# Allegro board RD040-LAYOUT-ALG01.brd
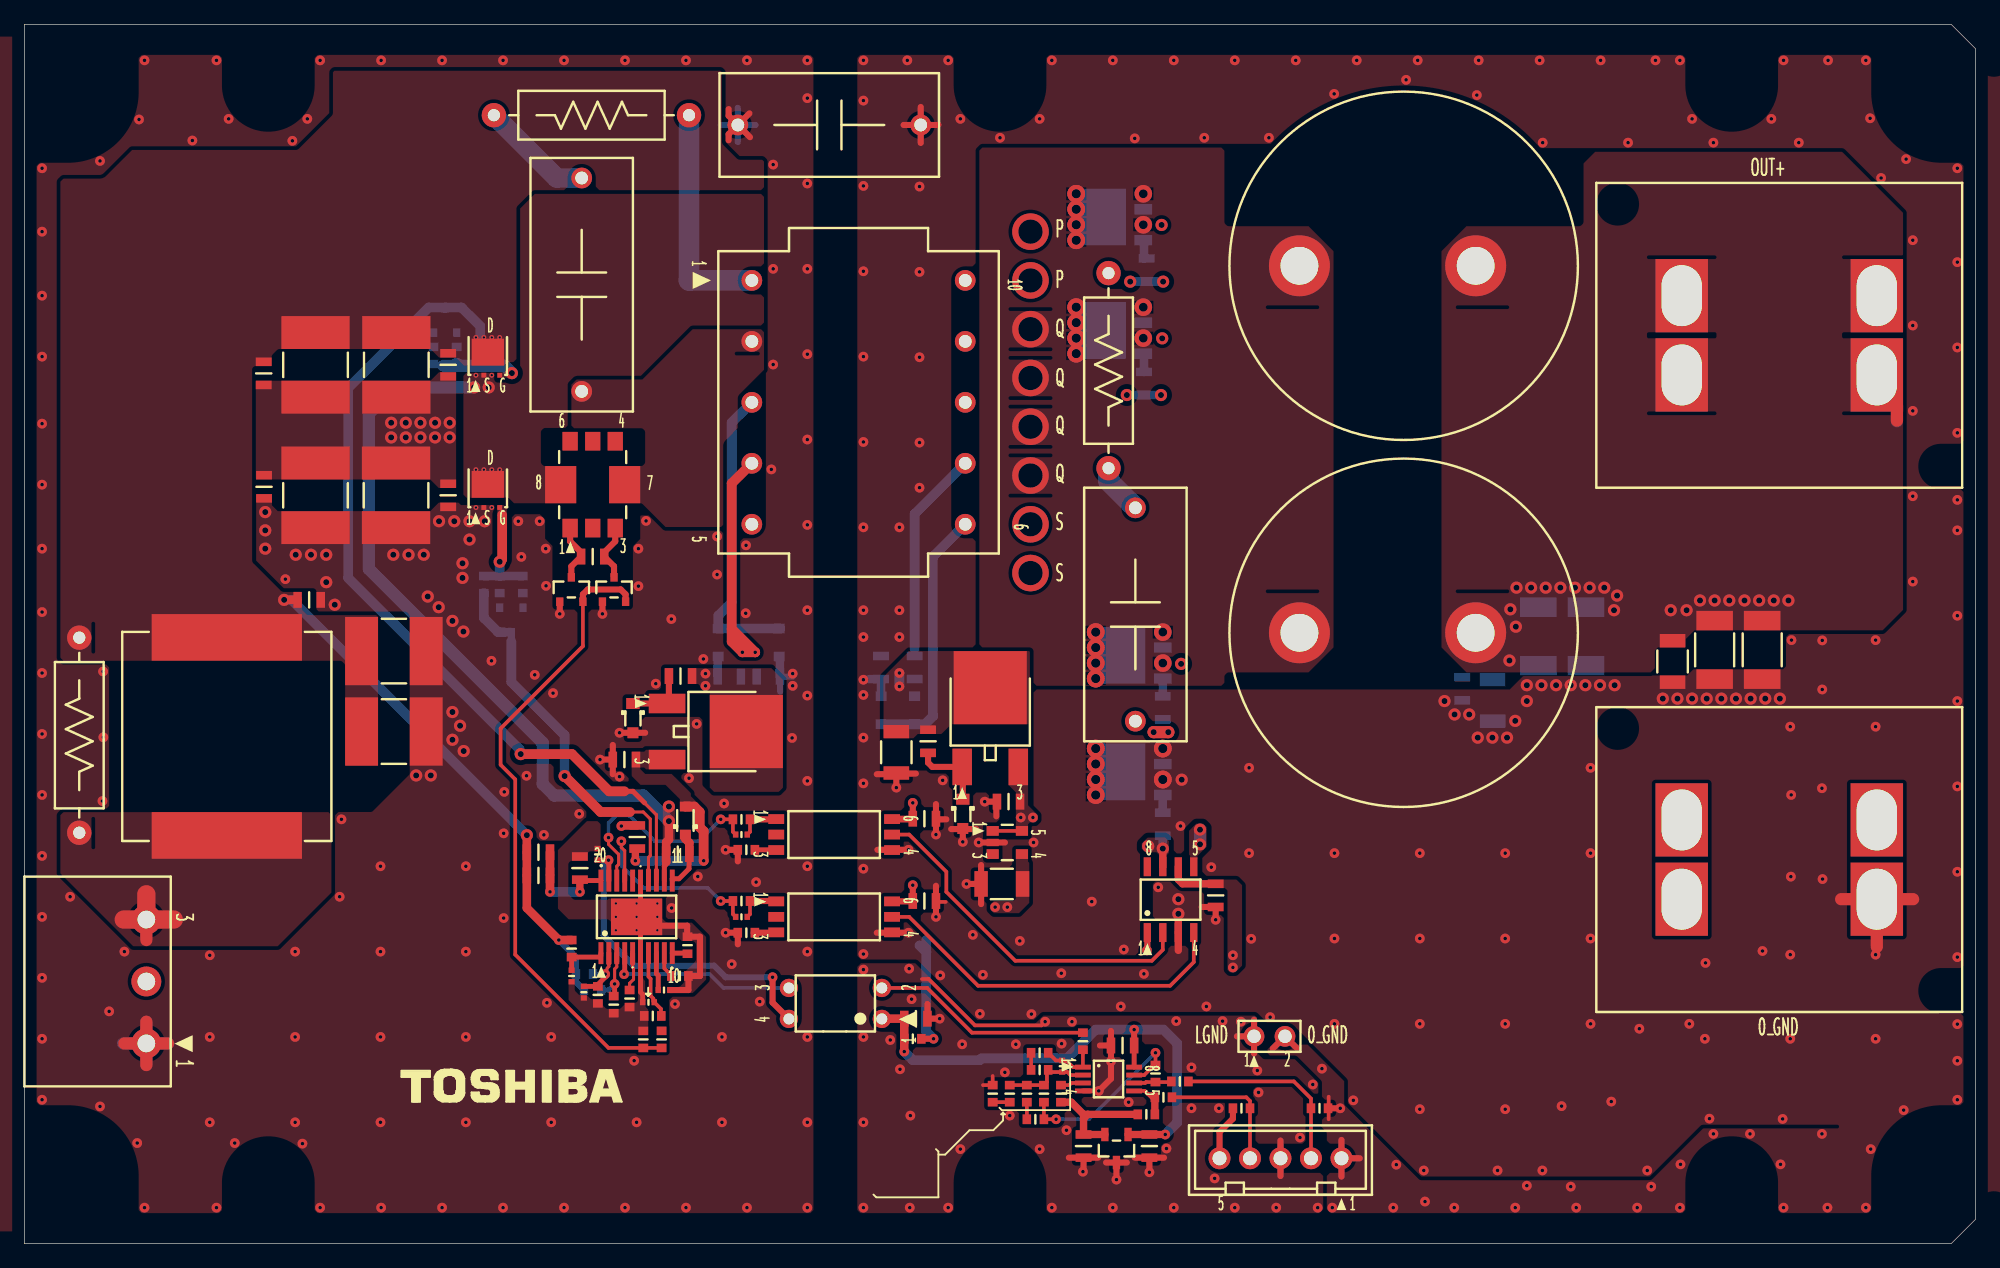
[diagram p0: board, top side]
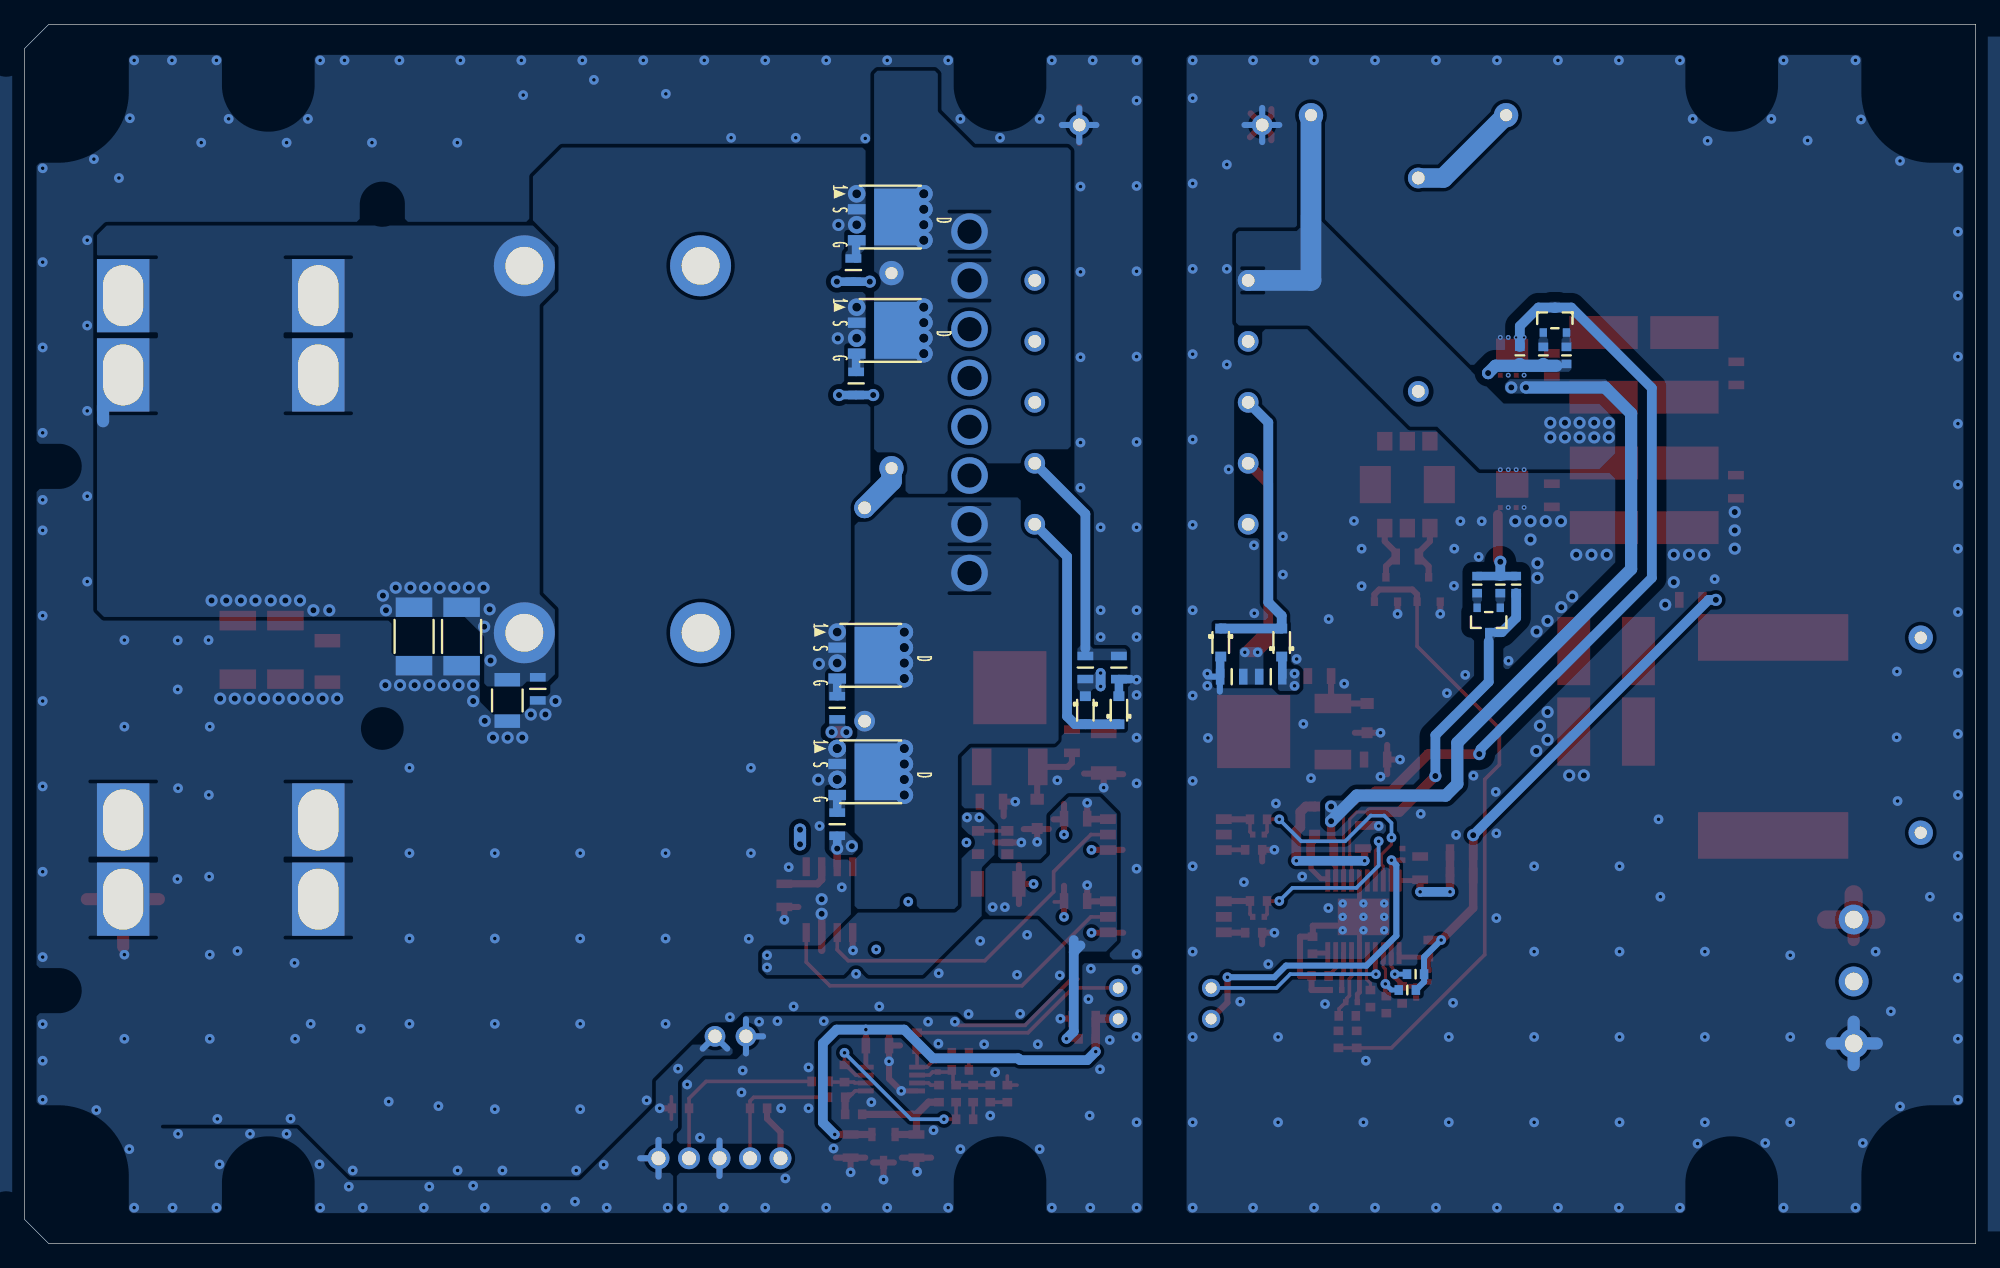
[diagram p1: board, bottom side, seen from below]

Outline 160 x 100 mm; copper layers: TOP, CONDUCTIVE2, CONDUCTIVE3, BOTTOM. Coordinates in mm from the lower left corner of the outline.
Outline path: 0,100 158,100 160,98 160,2 158,0 0,0 0,100

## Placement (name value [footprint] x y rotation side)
C1  -  [C_S_KCM55W_MU]  30.3 42 0 top
C2  -  [C_S_KCM55W_MU]  30.3 48.6 0 top
C3  -  [CHIP2012_GS_1]  23.35 52.8 0 top
C4  -  [C_S_KCM55W_MU]  23.88 72.08 270 top
C5  -  [C_S_KCM55W_MU]  30.5 72.08 270 top
C6  -  [CHIP2012_GS_1]  34.75 72.08 270 top
C7  -  [C_S_KCM55W_MU]  23.88 61.38 270 top
C8  -  [C_S_KCM55W_MU]  30.48 61.38 270 top
C9  -  [CHIP2012_GS_1]  34.75 61.38 270 top
C11  -  [CHIP2012_GS_1]  57.8 46.5 0 bottom
C12  -  [CHIP2012_GS_1]  61 46.5 0 bottom
C13  -  [CHIP2012_GS_1]  49.2 39.7 180 top
C14  -  [C_I_ECWH20222_PN]  66 91.75 0 top
C16  -  [C_I_ECQE2225_PN]  45.7 78.65 90 top
C21  -  [CHIP2012_GS_1]  50.25 33.35 270 top
C22  -  [CHIP2012_GS_1]  53.58 31.95 0 top
C23  -  [CHIP2012_GS_1]  45.55 30.8 90 top
C24  -  [CHIP1005_GS_2]  44.88 21.95 90 top
C25  -  [CHIP1005_GS_2]  45.88 20.62 90 top
C26  -  [CHIP1005_GS_2]  52.45 20.8 180 top
C27  -  [CHIP1608_GS_1]  54.38 24.48 90 top
C28  -  [CHIP1005_GS_2]  51.17 19.8 0 top
C29  -  [CHIP1005_GS_2]  47 31.93 90 top
C31  -  [CHIP1005_GS_2]  58.8 33.55 180 top
C32  -  [CHIP2012_GS_1]  73.8 34.85 0 top
C33  -  [CHIP1005_GS_2]  58.8 26.8 180 top
C34  -  [CHIP2012_GS_1]  73.8 28.1 0 top
C41  -  [CHIP3225_GS]  71.5 40.3 270 top
C42  -  [CHIP2012_GS_1]  80.7 36.25 180 top
C44  -  [CHIP3225_GS]  80.15 29.5 180 top
C46  -  [CHIP2012_GS_1]  97.69 28.56 90 top
C47  -  [CHIP2012_GS_1]  73 47.25 90 bottom
C48  -  [CHIP2012_GS_1]  70.25 47.25 270 bottom
C51  -  [C_I_ECQE2225_PN]  91.1 51.6 90 top
C52  -  [CHIP4532_TY]  124.15 49.8 270 bottom
C53  -  [CHIP4532_TY]  128.05 49.8 270 bottom
C54  -  [CHIP4532_TY]  138.6 48.7 270 top
C55  -  [CHIP4532_TY]  142.5 48.7 270 top
C56  -  [CHIP3225_GS]  135.15 47.75 270 top
C57  -  [CHIP3225_GS]  120.4 44.55 270 bottom
C58  -  [CHIP2012_GS_1]  117.9 45.5 270 bottom
C61  -  [CHIP2012_GS_1]  73.1 18.45 0 top
C62  -  [CHIP2012_GS_1]  90.05 16.25 180 top
C63  -  [CHIP1005_GS_2]  85.1 14.55 90 top
C64  -  [CHIP1608_GS_1]  83.25 14.25 180 top
C65  -  [CHIP1608_GS_1]  82.2 12.3 90 top
C66  -  [CHIP2012_GS_1]  92.25 8 270 top
C67  -  [CHIP2012_GS_1]  86.85 8 90 top
CN1  -  [TM_I_XW4A_03C1_H1_OM]  10 21.5 270 top
CN2  -  [TM_I_OP_1100_GS]  143.9 74.5 90 top
CN3  -  [TM_I_OP_1100_GS]  143.9 31.5 90 top
CN4  -  [CN_I_DF1B_5P_2_5DSA__1]  103 7 0 top
D1  -  [DI_S_SOT23_3_0_95_TS]  34.5 75.72 180 bottom
D2  -  [DI_S_SOT23_3_0_95_TS]  39.92 51.15 0 bottom
D3  -  [DI_S_SOT23_3_0_95_TS]  48.35 53.65 0 top
D4  -  [DI_S_SOT23_3_0_95_TS]  44.85 53.65 0 top
D5  -  [DI_S_SOD323_2_TS_A]  54.2 34.7 90 top
D6  -  [DI_S_SOD323_2_TS_A]  56.9 49.3 90 bottom
D7  -  [DI_S_SOD323_2_TS_A]  61.9 49.3 270 bottom
D8  -  [DI_S_SC90A_2_PN_A]  49.9 43.1 270 top
D9  -  [DI_S_SOD323_2_TS_A]  73 43.75 270 bottom
D10  -  [DI_S_SOD323_2_TS_A]  70.25 43.75 90 bottom
D11  -  [DI_S_SC90A_2_PN_A]  76.95 35.25 270 top
FB1  -  [CHIP1608_GS_1]  72.85 16.8 0 top
IC1  -  [IC_S_SOP_20E_0_65_TI]  50.2 26.8 0 top
IC2  -  [PH_S_TLP2767_TS]  66.4 33.55 270 top
IC3  -  [PH_S_TLP2767_TS]  66.4 26.8 270 top
IC4  -  [PH_I_TLP785_TS_1]  66.5 19.7 90 top
IC5  -  [IC_S_SOP_8_1_27_TI]  93.98 28.21 0 top
IC6  -  [IC_S_SOP_5_0_95_TS]  80.6 32.9 270 top
IC7  -  [IC_S_SOP_8_0_65_GS_2]  88.9 13.5 270 top
IC8  -  [IC_S_SOT23_3_0_95_GS]  89.55 7.8 180 top
J1  -  [HP_I_FFC_2AMEP1_HN]  102.1 17 0 top
L1  -  [L_S_IHLP6767GZ__01_V_1]  16.6 41.6 90 top
L2  -  [L_I_IHTH1125KZ_1R0_5_1]  113.1 80.2 0 top
L3  -  [L_I_IHTH1125KZ_1R0_5_1]  113.1 50.1 0 top
Q1  -  [TR_S_SON_ADVANCE_TS__1]  38 72.8 0 top
Q2  -  [TR_S_SON_ADVANCE_TS__1]  38 61.95 0 top
Q3  -  [TR_S_DPAK_3_2_3_TS]  57.2 42 270 top
Q4  -  [TR_S_DPAK_3_2_3_TS]  79.2 43.6 0 top
Q5  -  [TR_S_SOP_ADVANCE_TS__1]  90.6 38.7 270 bottom
Q6  -  [TR_S_SOP_ADVANCE_TS__1]  90.6 48.25 270 bottom
Q7  -  [TR_S_SOP_ADVANCE_TS__1]  89 74.9 270 bottom
Q8  -  [TR_S_SOP_ADVANCE_TS__1]  89 84.2 270 bottom
R1  -  [R_I_MOS2C_KO]  4.5 41.7 90 top
R2  -  [CHIP2012_GS_1]  19.62 71.38 90 top
R3  -  [CHIP2012_GS_1]  19.65 62.08 90 top
R4  -  [CHIP1608_GS_1]  37.38 72.85 270 bottom
R5  -  [CHIP1608_GS_1]  33.55 72.85 270 bottom
R6  -  [CHIP1608_GS_1]  35.45 72.85 270 bottom
R7  -  [CHIP1608_GS_1]  37.67 54.05 90 bottom
R8  -  [CHIP1608_GS_1]  40.88 54.05 90 bottom
R9  -  [CHIP1608_GS_1]  38.98 54.05 90 bottom
R11  -  [CHIP2012_GS_1]  53.8 46.55 0 top
R12  -  [R_I_MOS2C_KO]  46.5 92.55 180 top
R21  -  [CHIP2012_GS_1]  42.15 30.2 180 top
R22  -  [CHIP2012_GS_1]  42.15 32.1 180 top
R23  -  [CHIP1608_GS_1]  44.88 24.2 270 top
R24  -  [CHIP1608_GS_1]  45.92 22.1 0 bottom
R25  -  [CHIP1608_GS_1]  47.02 20.4 270 top
R26  -  [CHIP1608_GS_1]  46.6 20.8 0 bottom
R27  -  [CHIP1608_GS_1]  48.33 19.6 270 top
R28  -  [CHIP1608_GS_1]  49.62 20.1 270 top
R29  -  [CHIP1608_GS_1]  53.75 21.95 0 top
R30  -  [CHIP1608_GS_1]  51.52 18.68 0 top
R31  -  [CHIP1608_GS_1]  52.25 16.75 90 top
R32  -  [CHIP2012_GS_1]  46.6 56.35 0 top
R33  -  [CHIP1608_GS_1]  50.75 16.75 270 top
R36  -  [CHIP1608_GS_1]  58.8 34.8 0 top
R37  -  [CHIP1608_GS_1]  58.8 28.1 0 top
R38  -  [CHIP1608_GS_1]  59.2 32.3 180 top
R39  -  [CHIP1608_GS_1]  59.2 25.5 180 top
R43  -  [CHIP2012_GS_1]  74.1 41.2 90 top
R44  -  [CHIP2012_GS_1]  93.35 34.4 270 bottom
R45  -  [CHIP2012_GS_1]  93.35 43.95 270 bottom
R46  -  [CHIP2012_GS_1]  91.8 70.55 270 bottom
R47  -  [CHIP2012_GS_1]  92.03 79.85 270 bottom
R48  -  [R_I_MOS2C_KO]  88.9 71.6 270 top
R52  -  [CHIP1608_GS_1]  99.8 11.1 180 top
R53  -  [CHIP1608_GS_1]  106.2 11.1 0 top
R54  -  [CHIP1608_GS_1]  94.75 13.3 0 top
R55  -  [CHIP1608_GS_1]  93.4 12 0 top
R56  -  [CHIP1608_GS_1]  92.75 13.95 270 top
R57  -  [CHIP1608_GS_1]  92 10.6 0 top
R58  -  [CHIP1608_GS_1]  82.9 10.2 0 top
R59  -  [CHIP1608_GS_1]  83.6 12.3 270 top
R61  -  [CHIP1608_GS_1]  80.8 12.3 90 top
R62  -  [CHIP1608_GS_1]  83.25 15.65 180 top
R63  -  [CHIP1608_GS_1]  85 12.3 270 top
R64  -  [CHIP1608_GS_1]  86.8 16.6 270 top
R65  -  [CHIP1608_GS_1]  79.4 12.3 270 top
T1  -  [T_I_PC40EER28_GS]  68.4 69 270 top
T2  -  [T_S_53__C_MU]  46.6 62.25 0 top

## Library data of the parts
C1 C2 C4 C5 C7 C8 = KRM55W_MU: alternate symbols: ()
C3 C6 C9 C11-C13 C21-C23 C32 C34 C42 C46-C48 C58 C61 C62 C66 C67 R2 R3 R11 R21 R22 R32 R43-R47 = Chip2012_GS_1: alternate symbols: ()
C14 = ECWH20222_PN: alternate symbols: ()
C16 C51 = ECQE2225_PN: alternate symbols: ()
C24-C26 C28 C29 C31 C33 C63 = Chip1005_GS_2: alternate symbols: ()
C27 C64 C65 FB1 R4-R9 R23-R31 R33 R36-R39 R52-R59 R61-R65 = Chip1608_GS_1: alternate symbols: ()
C41 C44 C56 C57 = Chip3225_GS: alternate symbols: ()
C52-C55 = Chip4532_TY: alternate symbols: ()
CN1 = XW4A-03C1-H1_OM: alternate symbols: ()
CN2 CN3 = OP-1100_GS: alternate symbols: ()
CN4 = DF1B-5P-2.5DSA_HR: alternate symbols: ()
D1-D4 = TBAT54S_TS: alternate symbols: ()
D5-D7 D9 D10 = BAS316_TS_A: alternate symbols: ()
D8 D11 = DZ2J110M0L_PN_A: alternate symbols: ()
IC1 = LM5035M_TI: alternate symbols: ()
IC2 IC3 = TLP2767_TS: alternate symbols: ()
IC4 = TLP785_TS_1: alternate symbols: ()
IC5 = UCC2752*D_TI: alternate symbols: ()
IC6 = TAR5S**_TS: alternate symbols: ()
IC7 = ADA4805-2ARM_GS_2: alternate symbols: ()
IC8 = ADR280ART_GS: alternate symbols: ()
J1 = FFC-2AMEP1_HN: alternate symbols: ()
L1 = IHLP6767GZ****01_VS: alternate symbols: ()
L2 L3 = IHTH1125KZ**1R0*5A_VS: alternate symbols: ()
Q1 Q2 = TPN1200APL_TS_A: alternate symbols: ()
Q3 Q4 = 2SC5886A_TS: alternate symbols: ()
Q5-Q8 = TPHR6503PL_TS_A: alternate symbols: ()
R1 R12 R48 = MOS2C_KO: alternate symbols: ()
T1 = PC40EER28_GS: alternate symbols: ()
T2 = 53***C_MU: alternate symbols: ()

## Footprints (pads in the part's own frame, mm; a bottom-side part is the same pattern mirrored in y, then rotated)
C_I_ECQE2225_PN
  round 1.7 hole 1.05: 1(-8.75,0) 2(8.75,0)
C_I_ECWH20222_PN
  round 1.7 hole 1.05: 1(-7.5,0) 2(7.5,0)
C_S_KCM55W_MU
  rect 2.7x5.6 smd: 1(-2.65,0) 2(2.65,0)
CHIP1005_GS_2
  rect 0.45x0.5 smd: 1(-0.475,0) 2(0.475,0)
CHIP1608_GS_1
  rect 0.7x0.8 smd: 1(-0.7,0) 2(0.7,0)
CHIP2012_GS_1
  rect 0.7x1.3 smd: 1(-0.95,0) 2(0.95,0)
CHIP3225_GS
  rect 1.1x2.1 smd: 1(-1.7,0) 2(1.7,0)
CHIP4532_TY
  rect 1.6x3 smd: 1(-2.4,0) 2(2.4,0)
CN_I_DF1B_5P_2_5DSA__1
  round 1.8 hole 1.15: 1(5,0) 2(2.5,0) 3(0,0) 4(-2.5,0) 5(-5,0)
DI_S_SC90A_2_PN_A
  rect 0.9x0.9 smd: 1(1.2,0)
  rect 0.9x1.1 smd: 2(-1.2,0)
DI_S_SOD323_2_TS_A
  rect 0.8x0.9 smd: 1(1.15,0) 2(-1.15,0)
DI_S_SOT23_3_0_95_TS
  rect 0.6x0.7 smd: 1(-0.95,-1) 2(0.95,-1) 3(0,1)
HP_I_FFC_2AMEP1_HN
  round 1.7 hole 1.1: 1(-1.27,0) 2(1.27,0)
IC_S_SOP_5_0_95_TS
  rect 0.8x1 smd: 1(-0.95,-1.2) 3(0.95,-1.2) 4(0.95,1.2) 5(-0.95,1.2)
  rect 0.6x1 smd: 2(0,-1.2)
IC_S_SOP_8_0_65_GS_2
  rect 0.4x1.3 smd: 1(-0.975,-2.1) 2(-0.325,-2.1) 3(0.326,-2.1) 4(0.976,-2.1) 5(0.976,2.1) 6(0.326,2.1) 7(-0.325,2.1) 8(-0.975,2.1)
IC_S_SOP_8_1_27_TI
  rect 0.6x1.55 smd: 1(-1.905,-2.7) 2(-0.635,-2.7) 3(0.635,-2.7) 4(1.905,-2.7) 5(1.905,2.7) 6(0.635,2.7) 7(-0.635,2.7) 8(-1.905,2.7)
IC_S_SOP_20E_0_65_TI
  rect 0.4x1.8 smd: 1(-2.925,-2.975) 2(-2.275,-2.975) 3(-1.625,-2.975) 4(-0.975,-2.975) 5(-0.325,-2.975) 6(0.325,-2.975) 7(0.975,-2.975) 8(1.625,-2.975) 9(2.275,-2.975) 10(2.925,-2.975) 11(2.925,2.975) 12(2.275,2.975) 13(1.625,2.975) 14(0.975,2.975) 15(0.325,2.975) 16(-0.325,2.975) 17(-0.975,2.975) 18(-1.625,2.975) 19(-2.275,2.975) 20(-2.925,2.975)
  custom 0.75x0.75 smd: 21(0,0)
IC_S_SOT23_3_0_95_GS
  rect 0.6x1.1 smd: 1(-0.95,-1.15) 2(0.95,-1.15) 3(0,1.15)
L_I_IHTH1125KZ_1R0_5_1
  round 5 hole 3.1: 1(-8.547,0) 2(5.905,0)
L_S_IHLP6767GZ__01_V_1
  custom 0.956x0.956 smd: 1(-8.123,0) 2(8.123,0)
PH_I_TLP785_TS_1
  round 1.5 hole 0.9: 1(-1.27,-3.81) 2(1.27,-3.81) 3(1.27,3.81) 4(-1.27,3.81)
PH_S_TLP2767_TS
  rect 0.8x1.3 smd: 1(-1.27,-4.75) 2(0,-4.75) 3(1.27,-4.75) 4(1.27,4.75) 5(0,4.75) 6(-1.27,4.75)
R_I_MOS2C_KO
  round 2 hole 1: 1(-8,0) 2(8,0)
T_I_PC40EER28_GS
  round 1.7 hole 1.05: 1(-10,-8.75) 2(-5,-8.75) 3(0,-8.75) 4(5,-8.75) 5(10,-8.75) 6(10,8.75) 7(5,8.75) 8(0,8.75) 9(-5,8.75) 10(-10,8.75)
T_S_53__C_MU
  custom 0.312x0.312 smd: 1(-1.85,-3.562) 2(0,-3.562) 3(1.85,-3.562) 4(1.85,3.562) 5(0,3.562) 6(-1.85,3.562)
  custom 0.637x0.637 smd: 7(2.625,0) 8(-2.625,0)
TM_I_OP_1100_GS
  rect 6x4.3 hole 5x3.3: 1(-3.25,-8) 2(3.25,-8) 3(3.25,8) 4(-3.25,8)
TM_I_XW4A_03C1_H1_OM
  round 2.45 hole 1.45: 1(5.08,0) 2(0,0) 3(-5.08,0)
TR_S_DPAK_3_2_3_TS
  rect 1.6x3 smd: 1(-2.3,-4.5) 3(2.3,-4.5)
  rect 6x6 smd: 2(0,2)
TR_S_SON_ADVANCE_TS__1
  custom 0.55x0.55 smd: D(0,0.325)
  rect 0.4x0.4 smd: G(0.975,-1.575) S(-0.325,-1.575)
TR_S_SOP_ADVANCE_TS__1
  custom 0.938x0.938 smd: D(0,0.55)
  rect 0.85x1.45 smd: G(1.905,-2.75) S(-0.635,-2.75)

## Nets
I_10V: C13.1(TP-1) C21.2(TP-1) D5.1(TP-1) IC1.16 Q3.3
LGND: C61.2(TP-1) C62.2(TP-1) C66.2(TP-1) C67.1(TP-1) CN4.3 IC7.4 IC8.3 J1.1(TP-1) R65.1(TP-1)
O_5V: C32.1(TP-1) C34.1(TP-1) C44.1(TP-1) FB1.2(TP-1) IC2.6 IC3.6 IC6.4
O_10V: C42.1(TP-1) C46.2(TP-1) IC5.1 IC5.6 IC5.8 IC6.1 IC6.5 Q4.3
O_GND: C14.2(TP-1) C32.2(TP-1) C34.2(TP-1) C41.2(TP-1) C42.2(TP-1) C44.2(TP-1) C46.1(TP-1) C48.2(TP-1) C52.2(TP-1) C53.2(TP-1) C54.2(TP-1) C55.2(TP-1) C56.2(TP-1) C57.2(TP-1) C58.2(TP-1) CN3.1 CN3.2 CN3.3 CN3.4 CN4.1 D10.1(TP-1) D11.1(TP-1) IC2.4 IC3.4 IC5.3 IC6.2 J1.2(TP-1) Q5.S Q6.S Q7.S Q8.S R53.2(TP-1)
OUT+: C52.1(TP-1) C53.1(TP-1) C54.1(TP-1) C55.1(TP-1) C56.1(TP-1) C57.1(TP-1) C58.1(TP-1) CN2.1 CN2.2 CN2.3 CN2.4 CN4.5 L2.2(TP-1) L3.2(TP-1) R52.2(TP-1)
PN: C1.2(TP-1) C2.2(TP-1) C3.2(TP-1) C7.2(TP-1) C8.2(TP-1) C9.2(TP-1) C12.2(TP-1) C13.2(TP-1) C14.1(TP-1) C21.1(TP-1) C23.2(TP-1) C24.1(TP-1) C25.1(TP-1) C26.1(TP-1) C27.2(TP-1) C28.1(TP-1) C29.2(TP-1) CN1.1 D3.1 D4.1 D7.1(TP-1) D8.1(TP-1) IC1.6 IC1.15 IC1.21 Q2.S R3.1(TP-1) R25.2(TP-1) R27.2(TP-1) R28.2(TP-1) R29.2(TP-1) R30.1(TP-1) R33.1(TP-1) R38.2(TP-1) R39.2(TP-1)
N03975: C1.1(TP-1) C2.1(TP-1) C3.1(TP-1) C4.1(TP-1) C5.1(TP-1) C6.1(TP-1) L1.2(TP-1) Q1.D R1.2(TP-1) R2.2(TP-1) R21.2(TP-1) R22.2(TP-1) R23.1(TP-1) R24.1(TP-1) R26.1(TP-1)
N04057: C4.2(TP-1) C5.2(TP-1) C6.2(TP-1) C7.1(TP-1) C8.1(TP-1) C9.1(TP-1) R2.1(TP-1) R3.2(TP-1) R12.1(TP-1) T1.1
N07028: Q1.G R4.2(TP-1) R5.2(TP-1) R6.2(TP-1)
N07195: Q2.G R7.2(TP-1) R8.2(TP-1) R9.2(TP-1)
N07198: D1.3 IC1.13 R4.1(TP-1)
N07407: D2.3 IC1.14 R7.1(TP-1)
N07475: C22.1(TP-1) IC1.12 Q1.S Q2.D T2.8
N08432: CN1.3 L1.1(TP-1) R1.1(TP-1)
N09234: C24.2(TP-1) IC1.1 R23.2(TP-1)
N09291: C25.2(TP-1) IC1.2 R24.2(TP-1) R25.1(TP-1)
N09925: IC1.3 R26.2(TP-1) R27.1(TP-1)
N10150: IC1.4 IC4.3
N10207: IC1.5 R28.1(TP-1)
N10599: C26.2(TP-1) IC1.8
N10798: IC1.9 R29.1(TP-1)
N10927: C27.1(TP-1) IC1.10
N11642: C28.2(TP-1) IC1.7 R30.2(TP-1) R31.2(TP-1)
N12755: C22.2(TP-1) D5.2(TP-1) IC1.11
N12929: C23.1(TP-1) IC1.20 R21.1(TP-1) R22.1(TP-1)
N13908: C29.1(TP-1) IC1.19 IC4.4
N14012: C31.2(TP-1) IC1.18 R36.1(TP-1)
N14069: C33.2(TP-1) IC1.17 R37.1(TP-1)
N17106: Q5.G R44.1(TP-1)
N17193: Q6.G R45.1(TP-1)
N17255: Q7.G R46.1(TP-1)
N17317: Q8.G R47.1(TP-1)
N17411: C51.1(TP-1) Q5.D Q6.D
N17449: Q7.D Q8.D R48.1(TP-1)
N17555: IC5.7 R44.2(TP-1) R45.2(TP-1)
N17605: IC5.5 R46.2(TP-1) R47.2(TP-1)
N20539: L2.1(TP-1) L3.1(TP-1)
N24537: D6.1(TP-1) D7.2(TP-1) T1.3
N25173: C11.2(TP-1) C12.1(TP-1) T1.4
N25453: C11.1(TP-1) D6.2(TP-1) Q3.2 R11.2(TP-1)
N25757: D8.2(TP-1) Q3.1 R11.1(TP-1)
N27526: C16.2(TP-1) R12.2(TP-1)
N27553: C16.1(TP-1) T1.2 T2.7
N27715: C51.2(TP-1) R48.2(TP-1)
N28004: C41.1(TP-1) C47.1(TP-1) D9.2(TP-1) Q4.2 R43.2(TP-1)
N28016: D11.2(TP-1) Q4.1 R43.1(TP-1)
N32717: C61.1(TP-1) C62.1(TP-1) C66.1(TP-1) FB1.1(TP-1) IC4.1 IC7.8 IC8.1
N32808: IC4.2 R64.1(TP-1)
N32839: C63.2(TP-1) IC7.1 R62.1(TP-1) R64.2(TP-1)
N33727: IC7.7 R56.1(TP-1) R58.2(TP-1) R59.2(TP-1)
N33769: IC7.6 R54.1(TP-1) R56.2(TP-1)
N33837: IC7.5 R55.1(TP-1) R57.2(TP-1)
N33896: C67.2(TP-1) IC8.2 R57.1(TP-1) R63.2(TP-1)
N34516: C63.1(TP-1) C64.1(TP-1) C65.2(TP-1) IC7.2 R59.1(TP-1) R61.2(TP-1)
N35926: C65.1(TP-1) R58.1(TP-1)
N36200: C64.2(TP-1) R62.2(TP-1)
N37152: IC7.3 R63.1(TP-1)
N53493: CN4.2 R53.1(TP-1) R54.2(TP-1)
N53543: CN4.4 R52.1(TP-1) R55.2(TP-1)
N56552: R61.1(TP-1) R65.2(TP-1)
N75033: D1.1 R6.1(TP-1)
N75062: D1.2 R5.1(TP-1)
N76065: D2.1 R9.1(TP-1)
N76205: D2.2 R8.1(TP-1)
N78233: D4.3 R32.1(TP-1) T2.1
N78252: D3.3 R32.2(TP-1) T2.3
N78738: D3.2 D4.2 R31.1(TP-1) R33.2(TP-1)
N80775: IC2.3 R38.1(TP-1)
N80936: C31.1(TP-1) IC2.1 R36.2(TP-1)
N81048: C33.1(TP-1) IC3.1 R37.2(TP-1)
N87643: IC2.5 IC5.2
N87699: IC3.5 IC5.4
N106339: IC3.3 R39.1(TP-1)
N115099: D9.1(TP-1) D10.2(TP-1) T1.6
N115166: C47.2(TP-1) C48.1(TP-1) T1.7

Pads without a net: CN1 2; IC2 2; IC3 2; IC6 3; T1 5 8 9 10; T2 2 4 5 6

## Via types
v1: diameter 0.8, hole 0.3, TOP to BOTTOM, 395 vias
v2: diameter 1.45, hole 0.725, TOP to BOTTOM, 42 vias
v3: diameter 1, hole 0.5, TOP to BOTTOM, 109 vias
v4: diameter 3, hole 2, TOP to BOTTOM, 8 vias
v5: diameter 0.7, hole 0.2, TOP to BOTTOM, 9 vias
v6: diameter 0.4, hole 0.2, TOP to BOTTOM, 12 vias

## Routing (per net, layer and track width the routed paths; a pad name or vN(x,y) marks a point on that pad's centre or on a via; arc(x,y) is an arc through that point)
I_10V: length 12.3
  TOP w0.6: v1(50.1,31.4) 50.1,32.4 C21.2
  TOP w0.8: 54.17,35.85 D5.1 54.92,35.85 55.38,35.4 55.38,34.15 55.7,33.83 v1(55.7,31.4)
  BOTTOM w0.8: v1(50.1,31.4) v1(55.7,31.4)
LGND: length 59.3
  TOP w0.3: 78.6,13 R65.1 79.4,13.75 ; v1(83.7,18.2) 83.4,17.9 77.95,17.9 74.12,21.72 74.1,21.7 73.6,21.7
  TOP w0.4: IC7.4 88.12,12.52
  TOP w0.5: 103,5.55 CN4.3 103,8.45 ; C67.1 85.65,7.05 ; C67.1 88.05,7.05 ; C67.1 86.85,6.15 ; C62.2 v1(89.1,14.95) 89.1,13.53 v1(88.1,12.53) ; C62.2 89.1,17.45 ; C62.2 88.2,16.25 ; IC8.3 90.4,6.65 ; IC8.3 89.55,5.55 ; IC8.3 88.7,6.65 ; 74.05,19.65 C61.2 v1(75.05,18.45) ; J1.1 99.43,17 ; J1.1 100.83,18.35 ; J1.1 100.83,15.6 ; C66.2 93.45,7.05 ; C66.2 91.05,7.05 ; C66.2 92.25,6.15
  CONDUCTIVE2 w0.5: J1.1 100.83,18.38 ; J1.1 99.43,17 ; J1.1 100.83,15.6 ; 103,8.45 CN4.3 103,5.55
  CONDUCTIVE3 w0.5: J1.1 100.83,15.6 ; J1.1 100.83,18.3 ; J1.1 99.45,17 ; CN4.3 103,8.45
  BOTTOM w0.5: J1.1 99.43,17 ; J1.1 100.83,15.6 ; J1.1 100.83,18.4 ; 103,5.55 CN4.3 103,8.45
  vias: v1(68.8,22.48) v1(68.8,16.95) v1(68.8,9.95) v1(68.8,2.95) v1(71,16.7) v1(71.8,14.3) v1(72.55,22.55) v1(72.6,2.95) v1(72.65,10.5) v1(72.75,20.05) v1(75.75,2.95) v1(76.75,7.75) v1(76.9,16.35) v1(80.4,14.05) v1(80.8,10.5) v1(81.3,16.35) v1(83.25,7.75) v1(84.25,2.95) v1(85.05,16.4) v1(85.45,9.3) v1(85.9,18.2) v1(86.8,5.9) v1(89.25,2.95) v1(89.55,5.25) v1(90.55,11.6) v1(92.25,5.85) v1(93.65,7.8) v1(94.25,2.95) v1(94.45,18.25) v1(95.7,14.45) v1(95.7,11.1) v1(97.6,5.35) v1(97.95,11.1) v1(98.25,18.25) v1(99.25,2.95) v1(99.75,18.2) v1(101.1,14.2) v1(101.2,12.4) v1(102.65,2.95) v1(104.6,8.7) v1(105.65,13.05) v1(106.05,2.95)
O_5V: length 18.3
  TOP w0.5: FB1.2 v1(74.55,16.8) ; IC3.6 72.8,28.07 C34.1 ; v1(72.85,36.15) C32.1 72.85,34.8 ; v1(72.85,29.4) C34.1 ; C34.1 72.85,28
  TOP w0.55: C32.1 72.8,34.82 IC2.6
  CONDUCTIVE2 w0.8: v1(79.6,27.6) v1(80.6,27.6)
  CONDUCTIVE3 w0.8: v1(79.6,27.6) v1(80.6,27.6)
  BOTTOM w0.8: 73.95,23.91 73.95,17.4 v1(74.55,16.8) ; 73.95,23.91 73.95,24.9 ; 73.95,23.91 73.4,24.46
O_10V: length 12.1
  TOP w0.3: IC6.1 IC6.5
  TOP w0.5: v1(92.05,24.05) 92.08,24.05 IC5.1
  TOP w0.6: C46.2 94.97,29.51 94.62,29.86 IC5.6
  CONDUCTIVE2 w0.8: v1(99.1,22.65) v1(99.1,23.65) ; v1(81.7,34.95) v1(82.7,34.95)
  CONDUCTIVE3 w0.8: v1(99.1,22.65) v1(99.1,23.65) ; v1(81.7,34.95) v1(82.7,34.95)
O_GND: length 117.2
  TOP w0.3: 77.03,32.95 v1(76.95,32.95) ; R53.2 106.95,11.1 ; 106.95,11.1 106.95,12.05 ; 106.95,11.1 106.95,10.2 ; 75.55,28.02 74.75,28.02
  TOP w0.5: C14.2 73.5,90.28 ; C14.2 72.1,91.75 ; C14.2 74.95,91.75 ; C14.2 73.5,93.22 ; v1(72.5,25.5) 69.9,25.5 ; CN4.1 108,8.5 ; CN4.1 109.5,7 ; CN4.1 108,5.5 ; 79.7,36.25 v1(78.75,36.25) ; 79.7,36.25 79.7,36.3 ; 79.7,36.25 79.7,35.05 ; v1(72.5,32.3) 69.95,32.3 ; v1(107.9,11.1) 107,11.1 ; 96.53,27.61 C46.1 v1(97.69,26.56) ; C44.2 78.45,31.05 ; C44.2 78.45,27.85 ; C44.2 v1(77.25,29.5) ; 71.5,38.55 73.1,38.55 ; 76.95,34 v1(76.95,32.95) ; 76.95,34 76,34 ; 76.95,34 78.05,34 ; v1(74.75,33.55) 74.75,34.8 ; 74.75,34.8 C32.2 74.75,36.05 ; 74.75,34.8 75.6,34.8 ; 74.75,29.35 C34.2 v1(74.75,26.8) ; 80.4,32.9 IC6.2 v1(78.25,32.9) ; 69.9,38.5 71.5,38.5 v1(71.5,37.4) ; 104.37,16 J1.2 102.38,16
  TOP w0.6: 94.62,24.05 IC5.3 94.62,27.05
  TOP w1: CN3.1 154.88,28.25 ; CN3.1 148.97,28.25 ; CN3.1 151.9,24.35
  CONDUCTIVE2 w0.25: 122.22,52.88 121.9,52.98
  CONDUCTIVE2 w0.5: CN3.1 149.2,28.25 ; CN3.1 154.6,28.25 ; CN3.1 151.9,24.7 ; CN4.1 109.45,7 ; CN4.1 108,8.45 ; CN4.1 108,5.55 ; C14.2 73.5,93.15 ; C14.2 74.9,91.75 ; C14.2 73.5,90.35 ; C14.2 72.1,91.75 ; 102.38,16 J1.2 104.37,16
  CONDUCTIVE3 w0.25: 122.22,52.88 121.9,52.98
  CONDUCTIVE3 w0.5: CN3.1 151.9,24.7 ; CN3.1 154.6,28.25 ; CN3.1 149.2,28.25 ; C14.2 74.9,91.75 ; C14.2 72.1,91.75 ; C14.2 73.5,93.15 ; C14.2 73.5,90.35 ; 104.37,16 J1.2 102.38,16 ; 108,8.57 CN4.1 109.12,5.88
  BOTTOM w0.5: CN4.1 108,8.5 ; CN4.1 108,5.5 ; CN4.1 109.5,7 ; C14.2 73.5,93.12 ; C14.2 72.1,91.75 ; C14.2 73.5,90.35 ; C14.2 74.92,91.75 ; 102.37,16 J1.2 104.38,15.99
  BOTTOM w0.7: 69.3,46.3 C48.2 D10.1
  vias: v1(68.8,97.05) v1(68.8,93.75) v1(68.8,86.75) v1(68.8,79.75) v1(68.8,72.75) v1(68.8,65.75) v1(68.8,58.75) v1(68.8,51.95) v1(68.8,49.75) v1(68.8,46.25) v1(68.8,45) v1(68.8,41.5) v1(68.8,37.75) v1(68.8,30.75) v1(68.8,23.75) v1(71.75,58.75) v1(71.75,51.95) v1(71.75,49.75) v1(72.4,97.05) v1(73.4,86.7) v1(73.4,79.7) v1(73.4,72.7) v1(73.4,65.7) v1(73.4,62) v1(75.1,22) v1(75.3,38) v1(75.75,97.05) v1(76.75,92.25) v1(77.78,25.32) v1(78.35,18.85) v1(78.6,22.05) v1(80,90.7) v1(81.62,24.82) v1(82.58,18.82) v1(82.75,32.9) v1(83.25,92.25) v1(84.25,97.05) v1(85.03,22.18) v1(87.53,28.05) v1(89.25,97.05) v1(89.9,19.45) v1(90.15,24.12) v1(91.05,90.65) v1(91.8,22.12) v1(92.97,29.23) v1(94.25,97.05) v1(94.8,34.25) v1(96.75,90.7) v1(96.92,19.45) v1(97.33,30.88) v1(99.25,97.05) v1(100.42,39.02) v1(100.42,32.02) v1(100.6,25) v1(102.05,90.7) v1(102.15,18.57) v1(104.25,97.05) v1(106.4,14.35) v1(107.25,2.95) v1(107.4,94.3) v1(107.42,32.02) v1(107.42,25.02) v1(107.42,18.02) v1(108.97,11.75) v1(109.25,97.05) v1(112.25,2.95) v1(112.5,6.47) v1(113.3,95.45) v1(114.25,97.05) v1(114.42,32.02) v1(114.42,25.02) v1(114.42,18.02) v1(114.42,11.03) v1(114.75,6) v1(114.85,3.45) v1(117.25,2.95) v1(119.1,94.2) v1(119.25,97.05) v1(120.8,6) v1(121.42,32.02) v1(121.42,25.02) v1(121.42,18.02) v1(121.42,11.03) v1(122.25,2.95) v1(123.2,4.75) v1(124.25,97.05) v1(124.5,90.3) v1(124.47,6) v1(126.05,11.28) v1(126.8,4.67) v1(127.25,2.95) v1(128.43,39.02) v1(128.43,32.02) v1(128.43,25.02) v1(128.43,18.02) v1(129.25,97.05) v1(130.12,11.65) v1(131.5,90.3) v1(132.25,2.95) v1(132.43,17.62) v1(133.07,6) v1(133.4,4.67) v1(133.75,97.05) v1(135.75,97.05) v1(135.8,6.5) v1(135.75,2.95) v1(136.53,18.02) v1(136.75,92.25) v1(137.85,23.02) v1(137.8,16.8) v1(138.18,10.25) v1(138.5,90.3) v1(138.5,9) v1(141.5,9) v1(142.53,24) v1(143.25,92.25) v1(144,6.5) v1(144.25,97.05) v1(144.18,10.22) v1(144.25,2.95) v1(144.8,42.4) v1(144.85,30.1) v1(144.8,23.7) v1(144.8,16.8) v1(144.9,49.5) v1(144.88,36.8) v1(145.5,90.3) v1(147.43,49.48) v1(147.43,45.45) v1(147.4,37.35) v1(147.45,29.9) v1(147.4,9) v1(147.85,2.95) v1(147.9,97.05) v1(151,97.05) v1(151,2.95) v1(151.35,92.3) v1(151.4,7.75) v1(151.8,49.5) v1(151.8,42.4) v1(151.8,23.7) v1(151.8,16.8) v1(152.25,87.4) v1(154.1,10.95) v1(154.3,88.95) v1(154.85,82.3) v1(154.85,75.3) v1(154.85,68.3) v1(154.85,61.3) v1(154.85,54.3) v1(158.5,88.2) v1(158.5,80.5) v1(158.5,73.5) v1(158.5,66.5) v1(158.5,61) v1(158.5,58.5) v1(158.5,51.5) v1(158.5,44.5) v1(158.5,37.5) v1(158.5,30.5) v1(158.5,23.5) v1(158.5,18) v1(158.5,15) v1(158.5,11.8) v2(91.75,86.11) v2(91.75,83.56) v2(91.75,76.81) v2(91.75,74.27) v2(93.35,50.16) v2(93.35,47.62) v2(93.35,40.6) v2(93.35,40.6) v2(93.35,38.06) v2(93.35,38.06) v3(93.25,83.55) v3(93.3,74.25) v3(94.62,28.25) v3(94.62,27.05) v3(94.85,47.55) v3(94.9,38.05) v3(116.45,44.5) v3(117.28,43.4) v3(118.47,43.4) v3(119.17,41.5) v3(120.38,41.5) v3(121.58,41.5) v3(122.25,42.88) v3(123.2,45.8) v3(123.2,44.5) v3(124.4,45.8) v3(125.6,45.8) v3(126.8,45.8) v3(128,45.8) v3(129.2,45.8) v3(130.4,45.8) v3(134.35,44.7) v3(135.55,44.7) v3(136.75,44.7) v3(137.95,44.7) v3(139.15,44.7) v3(140.35,44.7) v3(141.55,44.7) v3(142.75,44.7) v3(143.95,44.7)
OUT+: length 129.9
  TOP w0.5: CN4.5 98,9.15 99.1,10.25 R52.2
  TOP w1: 153.55,68.75 153.55,67.5
  CONDUCTIVE2 w1: v3(144.65,52.75) v3(143.45,52.75) v3(142.25,52.75) v3(141.05,52.75) v3(139.8,52.75) v3(138.6,52.75) v3(137.4,52.75) 136.6,51.95 v3(136.3,51.95) v3(135,51.95) ; 130.35,53.15 v3(130.6,53.15) ; 130.35,53.15 v3(130.35,51.95) ; 130.35,53.15 130.2,53.15 v3(129.55,53.8) v3(128.35,53.8) v3(127.15,53.8) v3(125.95,53.8) v3(124.75,53.8) v3(123.55,53.8) v3(122.35,53.8)
  CONDUCTIVE3 w1: v3(122.35,53.8) v3(123.55,53.8) v3(124.75,53.8) v3(125.95,53.8) v3(127.15,53.8) v3(128.35,53.8) v3(129.55,53.8) 130.2,53.15 130.35,53.15 ; 130.35,53.15 v3(130.35,51.95) ; 130.35,53.15 v3(130.6,53.15) ; CN4.5 98,6.7 100,4.7 121.33,4.7 146.15,29.52 146.15,51.25 v3(144.65,52.75) v3(143.45,52.75) v3(142.25,52.75) v3(141.05,52.75) v3(139.8,52.75) v3(138.6,52.75) v3(137.4,52.75) 136.6,51.95 v3(136.3,51.95) v3(135,51.95)
  BOTTOM w1: 153.55,68.75 153.55,67.45
  vias: v3(121.85,52.02) v3(121.78,47.83) v3(122.3,50.6)
PN: length 85.4
  TOP w0.4: 50.52,25.7 50.52,20.62 50.7,20.45 50.7,19.85 ; 50.52,29.75 50.52,27.9
  TOP w0.5: 50.9,41.9 D8.1 v1(48.8,41.9) ; 57.75,90.5 57.75,91 C14.1 ; C13.2 48.3,39.7 ; C13.2 48.25,38.5 ; C13.2 48.25,40.9 ; C13.2 v1(47.2,39.7) ; 52.95,20.8 54.45,20.8 R29.2 55.4,21.95 55.4,25.18 C27.2 54.35,25.18 54.35,26.07 51.9,26.07 ; 58.5,31.35 R38.2 v1(57.5,32.3) ; C14.1 59.5,90.75 ; C14.1 59.45,92.7 ; C14.1 57.75,92.5 57.75,93.05 ; v1(47.4,51.65) D3.1 ; v1(43.9,51.65) D4.1 ; v1(57.5,25.5) R39.2 58.5,24.55
  TOP w0.7: 48.95,34.3 C21.1
  TOP w1: CN1.1 11.78,16.42 ; CN1.1 10,18.2 ; CN1.1 10,14.64 ; CN1.1 8.2,16.42
  CONDUCTIVE2 w0.5: C14.1 58.5,93.05 ; C14.1 59.8,91.75 ; C14.1 58.5,90.45 ; C14.1 57.2,91.75 ; CN1.1 8.32,16.42 ; CN1.1 10,18.09 ; CN1.1 11.68,16.42 ; CN1.1 10,14.74
  CONDUCTIVE3 w0.5: C14.1 57.2,91.75 ; C14.1 59.8,91.75 ; C14.1 58.5,90.45 ; C14.1 58.5,93.05 ; CN1.1 10,14.74 ; CN1.1 8.32,16.42 ; CN1.1 10,18.09 ; CN1.1 11.68,16.42
  BOTTOM w0.5: C14.1 58.5,93.15 ; C14.1 57.1,91.75 ; C14.1 58.5,90.35 ; C14.1 59.95,91.75 ; 61.98,45.27 61.98,46.5 63,46.5
  BOTTOM w0.7: C12.2 61.95,48.1
  BOTTOM w1: CN1.1 8.1,16.42 ; CN1.1 11.8,16.42 ; CN1.1 10,14.65 ; CN1.1 10,18.2
  vias: v1(1.45,88.2) v1(1.45,83) v1(1.45,77.75) v1(1.45,72.75) v1(1.45,67.25) v1(1.45,62.25) v1(1.45,57) v1(1.45,51.8) v1(1.45,46.8) v1(1.45,41.8) v1(1.45,36.8) v1(1.45,31.8) v1(1.45,26.8) v1(1.45,21.8) v1(1.45,16.8) v1(1.45,11.8) v1(3.75,28.45) v1(6.2,88.8) v1(6.2,11.25) v1(6.4,36.3) v1(6.45,46.92) v1(6.47,41.52) v1(6.95,19.05) v1(8.2,23.95) v1(9.25,8.25) v1(9.4,92.2) v1(9.85,97.05) v1(9.85,2.95) v1(13.78,90.47) v1(15.2,23.65) v1(15.2,16.95) v1(15.2,9.95) v1(15.75,97.05) v1(15.75,2.95) v1(16.75,92.25) v1(17.25,8.25) v1(21.4,54.5) v1(21.98,90.45) v1(22.2,23.95) v1(22.2,16.95) v1(22.2,9.95) v1(22.8,8.2) v1(23.2,92.25) v1(24.25,97.05) v1(24.25,2.95) v1(25.85,28.45) v1(26,34.8) v1(29.25,97.05) v1(29.2,30.95) v1(29.2,23.95) v1(29.2,16.95) v1(29.2,9.95) v1(29.25,2.95) v1(34.25,97.05) v1(34.25,2.95) v1(36.2,30.95) v1(36.2,23.95) v1(36.2,16.95) v1(36.2,9.95) v1(38.3,47.8) v1(39.25,97.05) v1(39.25,2.95) v1(39.3,33.65) v1(39.3,26.7) v1(39.35,37.05) v1(40.5,59.25) v1(40.75,56.33) v1(41.17,38.38) v1(41.85,46.65) v1(42.25,59.25) v1(42.6,33.52) v1(42.75,57) v1(42.77,53.95) v1(42.85,19.75) v1(43.2,16.95) v1(43.2,9.95) v1(43.35,45.15) v1(44.25,97.05) v1(44.25,2.95) v1(45.5,35.25) v1(48.8,38.3) v1(48.95,34.25) v1(49.25,97.05) v1(49.25,2.95) v1(50,15) v1(50.2,9.95) v1(50.35,57) v1(50.35,53.92) v1(50.98,59.27) v1(51.77,45.92) v1(53.05,51.23) v1(53.08,27.52) v1(53.35,19.65) v1(54.25,97.05) v1(54.25,2.95) v1(54.5,38.17) v1(55.12,42.62) v1(55.22,30.11) v1(55.67,47.95) v1(56.8,58) v1(56.8,54.88) v1(57.2,16.95) v1(57.2,9.95) v1(57.38,36.1) v1(58,22.93) v1(59.15,51.7) v1(59.25,97.05) v1(59.17,57.27) v1(59.25,2.95) v1(60,29.65) v1(60.3,19.85) v1(61.25,63.5) v1(61.4,88.5) v1(61.4,79.95) v1(61.4,72.1) v1(63,46.75) v1(63,45.75) v1(62.95,41.48) v1(64.2,97.05) v1(64.2,93.95) v1(64.2,86.95) v1(64.2,79.95) v1(64.2,72.95) v1(64.2,65.95) v1(64.2,58.95) v1(64.2,51.95) v1(64.2,44.95) v1(64.2,37.95) v1(64.2,30.95) v1(64.2,23.95) v1(64.2,16.95) v1(64.2,9.95) v1(64.2,2.95) v3(19.75,60) v3(19.75,58.5) v3(19.75,57) v3(22.25,56.5) v3(23.5,56.5) v3(24.75,56.5) v3(24.75,54.25) v3(25.45,52.4) v3(30.25,56.5) v3(31.5,56.5) v3(32.12,38.4) v3(32.75,56.5) v3(33.08,53.08) v3(33.33,38.4) v3(34,59.25) v3(33.98,52.2) v3(35.1,51.08) v3(35.1,43.6) v3(35.1,41.33) v3(35.25,59.25) v3(35.73,42.48) v3(35.92,55.8) v3(35.92,54.6) v3(36,50.2) v3(36.02,40.4) v3(36.5,59.25) v3(36.5,57.75) v3(37.75,59.25) v5(48.5,27.9) v5(48.5,26.8) v5(48.5,25.7) v5(50.2,27.9) v5(50.2,26.8) v5(50.2,25.7) v5(51.9,27.9) v5(51.9,26.8) v5(51.9,25.7) v6(37.02,60.38) v6(38.33,60.38)
N03975: length 44.7
  TOP w0.7: C3.1 v3(21.3,52.8) ; v3(41.2,33.5) R22.2 R21.2 41.2,27.52 v1(43.83,24.9) R23.1
  BOTTOM w0.5: v1(43.83,24.9) 45.23,23.5 R24.1 45.23,21.48 R26.1
  BOTTOM w0.8: v3(21.3,52.8) 21.9,52.8 v3(41.2,33.5)
  vias: v6(37.02,74.33) v6(37.67,74.33) v6(38.33,74.33) v6(38.98,74.33)
N04057: length 18.7
  BOTTOM w1.7: T1.1 54.5,79 R12.1
  vias: v3(30.07,67.33) v3(30.07,66.12) v3(31.27,67.33) v3(31.27,66.12) v3(32.48,67.33) v3(32.48,66.12) v3(33.67,67.33) v3(33.67,66.12) v3(34.88,67.33) v3(34.88,66.12)
N07028: length 6.1
  BOTTOM w1: 37.38,72 39.38,72 v3(39.98,71.4) ; 37.38,72 R4.2 ; 37.38,72 35.45,72 ; R6.2 35.45,72 ; 35.45,72 34.38,72
N07195: length 8.3
  TOP w0.8: v3(38.98,55.92) 39.17,56.12 39.17,59.77
  BOTTOM w0.7: R7.2 R9.2 R8.2
  BOTTOM w0.8: R9.2 v3(38.98,55.92)
N07198: length 70.4
  TOP w0.25: 51.83,30.62 51.83,35.17 50.85,36.15
  TOP w0.4: 49.2,37.1 49.9,37.1 50.85,36.15 ; IC1.13 51.83,30.62
  TOP w0.8: 49.2,37.1 47.95,37.1 44.9,40.15 v3(40.7,40.15)
  BOTTOM w0.8: v3(40.7,40.15) 40.6,40.25 40.6,40.55 26.55,54.6 26.55,70.17 33.15,76.78 34.5,76.78 ; 34.5,76.78 35.85,76.78 37.38,75.25 R4.1 ; 34.5,76.78 D1.3
N07407: length 31.9
  TOP w0.25: 49.65,35.4 50.75,35.4 51.33,34.83 51.33,31.82 51.17,31.68 51.17,30.62
  TOP w0.4: IC1.14 51.17,30.62
  TOP w0.8: v3(44.3,38.35) 47.25,35.4 49.65,35.4
  BOTTOM w0.6: D2.3 39.92,49.4
  BOTTOM w0.7: 39.88,50.15 39.33,50.15
  BOTTOM w0.8: 39.92,49.4 39.92,46.08 44.3,41.7 v3(44.3,38.35) ; R7.1 37.67,51.33 38.85,50.15 39.3,50.15
N07475: length 68
  TOP w0.4: C22.1 52.48,31.95 52.48,30.95 ; 52.48,30.95 52.77,31.25 52.77,31.5 ; 52.48,30.95 IC1.12
  TOP w0.7: v3(52.85,34.65) 52.85,33.15 52.62,32.92 C22.1
  CONDUCTIVE2 w1: v3(36.88,70.22) v3(38.08,70.22) ; v3(52.85,34.65) v3(52.85,35.85)
  CONDUCTIVE3 w1: v3(36.88,70.22) v3(38.08,70.22) ; v3(52.85,34.65) v3(52.85,35.85)
  BOTTOM w1: v3(36.88,70.22) 30.39,70.22 28.25,68.09 28.25,55.33 42.5,41.08 42.5,37.7 43.45,36.75 50.75,36.75 v3(52.85,34.65)
  vias: v6(37.02,71.22) v6(37.02,63.48) v6(37.67,63.48) v6(38.33,71.22) v6(38.33,63.48) v6(38.98,63.48)
N08432: length 7.8
  TOP w1: CN1.3 10,24.9
  TOP w1.5: CN1.3 10,28.65 ; CN1.3 12.25,26.58 ; CN1.3 8.15,26.58
N09234: length 3.8
  TOP w0.4: IC1.1 47.25,23.5 R23.2 C24.2
N09291: length 5.2
  TOP w0.25: 47.92,22.98 47.92,22.73 47.8,22.6 v1(47.62,22.1)
  TOP w0.4: C25.2 R25.1 47.02,21.25 47.62,21.85 v1(47.62,22.1) ; 47.92,22.98 47.92,23.82
  BOTTOM w0.4: R24.2 v1(47.62,22.1)
N09925: length 4.9
  TOP w0.25: v1(48.4,21.3) 48.4,22.52 48.58,22.7 48.58,23.12
  TOP w0.4: v1(48.4,21.3) 48.4,20.38 R27.1 ; IC1.3 48.58,23.12
  BOTTOM w0.4: R26.2 47.9,20.8 v1(48.4,21.3)
N10150: length 15.7
  TOP w0.4: v1(49.17,22.1) 49.23,22.15 IC1.4
  BOTTOM w0.3: IC4.3 57.33,20.97 56.2,22.1 v1(49.17,22.1)
N10207: length 3.2
  TOP w0.25: R28.1 49.62,21.35 49.95,21.68 49.95,22.6 49.88,22.68 49.88,22.98
  TOP w0.4: 49.88,22.98 IC1.5
N10599: length 3.1
  TOP w0.4: IC1.8 51.83,22.15 51.98,22 C26.2
N10798: length 2.1
  TOP w0.3: IC1.9 52.48,22.57 53.05,22 R29.1
N10927: length 1.3
  TOP w0.4: IC1.10 54.38,23.82 ; 54.38,23.82 C27.1 ; 54.38,23.82 54.4,23.82
N11642: length 5.6
  TOP w0.3: IC1.7 51.17,21.9 51.35,21.73 51.35,20.32 51.58,20.1 51.58,19.88 C28.2 52.2,19.25 52.2,18.7 R30.2
N12755: length 4.8
  TOP w0.4: 54.52,31.95 54.5,31.95 54.5,30.75 53.67,29.93 53.12,29.93 IC1.11
  TOP w0.7: 54.52,31.95 54.52,32.88 54.2,33.2 D5.2
N12929: length 8.4
  TOP w0.4: IC1.20 45.55,29.77
  TOP w0.6: v1(45.55,28.85) C23.1
  TOP w0.7: v1(43.1,28.85) R21.1 R22.1
  BOTTOM w0.8: v1(43.1,28.85) v1(45.55,28.85)
N13908: length 28.2
  TOP w0.4: 47.92,29.77 47.92,31.43 v1(47.9,31.45) C29.1
  TOP w0.5: v1(61.35,21.85) 61.35,19.77 IC4.4
  BOTTOM w0.5: v1(47.9,31.45) 47.5,31.05 47.5,25.25 49.95,22.8 56.55,22.8 57.5,21.85 v1(61.35,21.85)
N14012: length 18.5
  TOP w0.25: IC1.18 48.58,30.95 48.73,31.1 48.73,31.93 47.9,32.75 v1(47.9,33.3)
  TOP w0.3: C31.2 58.1,33.77 R36.1 v1(57.1,34.8)
  BOTTOM w0.3: v1(47.9,33.3) 47.9,34.5 48.5,35.1 49.6,35.1 51.7,33 55.3,33 v1(57.1,34.8)
N14069: length 17.1
  TOP w0.25: 49.23,30.62 49.23,32.23 48.95,32.5 v1(48.95,33)
  TOP w0.3: v1(57.1,28.1) R37.1 58.1,27.02 C33.2
  TOP w0.4: 49.23,30.62 IC1.17
  BOTTOM w0.3: v1(57.1,28.1) 56.02,29.18 50.77,29.18 48.95,31 v1(48.95,33)
N17106: length 1.5
  BOTTOM w0.7: R44.1 Q5.G 93.35,36.85
N17193: length 1.4
  BOTTOM w0.7: R45.1 Q6.G
N17255: length 1.5
  BOTTOM w0.7: R46.1 91.8,73
N17317: length 1.5
  BOTTOM w0.7: 91.8,80.8 91.8,82.3
N17411:
  vias: v2(87.85,50.16) v2(87.85,50.16) v2(87.85,48.88) v2(87.85,48.88) v2(87.85,47.62) v2(87.85,47.62) v2(87.85,46.34) v2(87.85,46.34) v2(87.85,40.6) v2(87.85,40.6) v2(87.85,39.34) v2(87.85,39.34) v2(87.85,38.06) v2(87.85,38.06) v2(87.85,36.8) v2(87.85,36.8) v4(82.5,59) v4(82.5,55)
N17449:
  vias: v2(86.25,86.11) v2(86.25,86.11) v2(86.25,84.83) v2(86.25,84.83) v2(86.25,83.56) v2(86.25,83.56) v2(86.25,82.3) v2(86.25,82.3) v2(86.25,76.81) v2(86.25,76.81) v2(86.25,75.53) v2(86.25,75.53) v2(86.25,74.27) v2(86.25,74.27) v2(86.25,73) v2(86.25,73) v4(82.5,83) v4(82.5,79)
N17555: length 7.9
  TOP w0.6: IC5.7 93.35,32.37
  TOP w1: v3(93.8,41.95) v3(92.6,41.95)
  CONDUCTIVE2 w1: v3(93.35,32.4) 93.15,32.6 v3(92.15,32.6) ; v3(93.8,41.95) v3(92.6,41.95)
  CONDUCTIVE3 w1: v3(93.8,41.95) 93.2,41.35 v3(92.6,41.95)
  BOTTOM w0.7: R44.2 v3(93.35,32.4)
N17605: length 41.1
  CONDUCTIVE2 w1: v3(96.4,32.75) v3(96.4,33.95)
  CONDUCTIVE3 w1.6: 94.92,65.67 96.7,63.9 96.7,33.25
  BOTTOM w0.7: v3(93.38,78.9) R47.2 v3(90.67,78.9) ; v3(93.2,69.6) R46.2 v3(90.4,69.6)
  BOTTOM w1: v3(96.4,32.75) v3(96.4,33.95)
N20539:
  vias: v4(82.5,75) v4(82.5,71) v4(82.5,67) v4(82.5,63)
N24537: length 24.7
  BOTTOM w0.8: 61.95,50.45 D7.2 D6.1 56.9,51.5 58,52.6 58,67.35 T1.3
N25173: length 22.4
  TOP w0.8: 58,50.42 58,62.35 T1.4 ; 58,50.42 58,49.38 v1(58.88,48.5) v1(59.92,48.5) 58,50.42
  CONDUCTIVE2 w0.8: v1(58.88,48.5) v1(59.92,48.5)
  CONDUCTIVE3 w0.8: v1(58.88,48.5) v1(59.92,48.5)
N25453: length 3.7
  CONDUCTIVE2 w0.8: v1(55.85,45.75) v1(55.85,46.75)
  CONDUCTIVE3 w0.8: v1(55.85,45.75) v1(55.85,46.75)
  BOTTOM w0.7: D6.2 56.85,48.1 C11.1
N25757: length 5.2
  TOP w0.5: D8.2 Q3.1 52.85,44.3 R11.1
N27526: length 9.3
  BOTTOM w1.6: R12.2 43.65,87.4 C16.2
N27715: length 4.2
  BOTTOM w1.7: R48.2 88.9,62.55 C51.2
N28004: length 3.3
  CONDUCTIVE2 w0.8: v1(71.75,45.7) v1(71.75,46.8)
  CONDUCTIVE3 w0.8: v1(71.75,45.7) v1(71.75,46.8)
  BOTTOM w0.8: v1(71.75,46.8) v1(71.75,45.7)
N28016: length 6.4
  TOP w0.5: D11.2 76.95,39.1 Q4.1 74.45,39.1 74.1,39.45 R43.1
N32717: length 42.7
  TOP w0.4: IC7.8 91,16.2
  TOP w0.5: 91,16.2 C62.1 v1(91,17.55)
  TOP w0.6: IC8.1 C66.1 v1(93.55,8.95)
  TOP w0.7: IC4.1 70.33,18.45 C61.1 FB1.1 v1(72.15,15.75)
  BOTTOM w0.8: v1(93.55,8.95) 94.53,9.93 94.53,16.43 93.4,17.55 v1(91,17.55) 87.85,17.55 85.5,15.2 78.5,15.2 78.35,15.05 72.85,15.05 v1(72.15,15.75)
N32808: length 18
  TOP w0.3: IC4.2 74.03,20.97 77.7,17.3 R64.1
N32839: length 4.8
  TOP w0.3: R62.1 84.58,15.03 C63.2 85.15,15.03 85.22,14.95 85.51,14.95 85.99,14.47 IC7.1 R64.2
N33727: length 15.9
  TOP w0.3: v1(84.6,10.2) R58.2 R59.2 ; IC7.7 91.82,13.82 92.65,14.65 R56.1 v1(92.75,15.65)
  BOTTOM w0.3: v1(84.6,10.2) 87.3,10.2 v1(92.75,15.65)
N33769: length 3.1
  TOP w0.3: IC7.6 91.9,13.17 91.98,13.25 R56.2 94,13.25 R54.1
N33837: length 3.7
  TOP w0.3: 92.15,12.25 91.88,12.52 IC7.5 ; 92.15,12.25 92.5,11.9 R55.1 ; 92.15,12.25 92.5,12.25
  TOP w0.6: R57.2 R55.1
N33896: length 10.7
  TOP w0.6: 86.85,10.6 85.85,11.6 R63.2 84.95,11.6 ; 86.85,10.6 87.2,10.6 ; 86.85,10.6 86.85,10.25 ; 86.85,10.25 87.2,10.6 ; 86.85,10.25 C67.2 IC8.2 ; 87.2,10.6 R57.1
N34516: length 7.3
  TOP w0.3: IC7.2 85.78,13.82 85.53,14.07 C63.1 84.1,14.07 C64.1 83.85,14.25 83.85,13.25 R59.1 C65.2 R61.2 80.75,13
N35926: length 1.4
  TOP w0.3: R58.1 C65.1
N36200: length 1.4
  TOP w0.3: C64.2 R62.2
N37152: length 1.9
  TOP w0.3: R63.1 85.68,13 85.85,13.17 IC7.3
N53493: length 15.6
  TOP w0.3: 95.4,13.3 R54.2 104.1,13.3 105.5,11.9 R53.1 CN4.2
N53543: length 11.2
  TOP w0.3: R55.2 100.2,12 100.5,11.7 R52.1 CN4.4
N56552: length 1.4
  TOP w0.3: R61.1 R65.2
N78233: length 4.7
  TOP w0.5: D4.3 44.85,55.55 R32.1 45.65,56.7 44.75,57.6 T2.1
N78252: length 4.7
  TOP w0.5: T2.3 48.45,57.6 47.55,56.7 R32.2 48.35,55.55 D3.3
N78738: length 52.4
  TOP w0.3: D4.2 45.8,49 39.05,42.25 39.05,39.27 40.25,38.08 40.25,23.7 47.9,16.05 R33.2 R31.1
  TOP w0.5: D4.2 45.8,53.25 46.2,53.65 48.9,53.65 49.3,53.25 D3.2
N80775: length 1.9
  TOP w0.4: 59.8,32.3 R38.1 61.6,32.3 IC2.3
N80936: length 3.6
  TOP w0.3: R36.2 59.5,33.77 C31.1
  TOP w0.5: R36.2 61.65,34.8 ; 61.65,34.8 61.7,34.8 ; 61.65,34.8 IC2.1
N81048: length 3.6
  TOP w0.3: R37.2 59.5,27.02 C33.1
  TOP w0.5: R37.2 61.6,28.1 IC3.1
N87643: length 29.2
  TOP w0.3: IC2.5 72.55,33.55 75.6,30.5 75.6,28.85 81.25,23.2 92.45,23.2 93.35,24.1 IC5.2
N87699: length 30.4
  TOP w0.3: 71.1,26.8 IC3.5 72.55,26.8 78.2,21.15 93.95,21.15 95.89,23.09 IC5.4
N106339: length 1.9
  TOP w0.5: IC3.3 61.6,25.5 R39.1 59.8,25.5
N115099: length 21.4
  BOTTOM w0.8: D10.2 D9.1 73.85,42.6 74.5,43.25 74.5,56.35 T1.6
N115166: length 16.9
  BOTTOM w0.8: 73,48.8 73,59.85 T1.7

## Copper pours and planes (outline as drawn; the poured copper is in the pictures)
I_10V on TOP: 53.85,35.45 53.78,35.48 53.75,35.55 53.75,36.45 52.58,37.62 50.57,37.62 50.53,37.63 50.5,37.65 49.83,38.32 49.81,38.35 49.8,38.39 49.8,40.3 49.81,40.34 49.85,40.35 50.83,40.35 50.96,40.49 50.98,40.5 51,40.5 54.15,40.5 54.19,40.49 54.2,40.45 54.2,38.95 54.19,38.91 54.15,38.9 51,38.9 50.98,38.9 50.96,38.91 50.83,39.05 50.5,39.05 50.5,38.92 50.9,38.52 53.03,38.52 53.07,38.52 53.1,38.5 54.62,36.98 54.64,36.95 54.65,36.91 54.65,36.69 55.22,36.12 55.24,36.09 55.25,36.05 55.25,35.55 55.22,35.48 55.15,35.45
LGND on TOP: 101.24,8.2 101.2,8.21 101.17,8.23 100.98,8.42 100.96,8.45 100.95,8.49 100.95,10.36 100.96,10.41 101.11,10.57 101.15,10.72 101.15,11.47 101.1,11.64 100.98,11.76 100.95,11.79 100.93,11.82 100.89,11.93 100.82,12.02 100.78,12.06 100.76,12.09 100.75,12.13 100.75,12.56 100.76,12.6 100.78,12.63 100.97,12.82 101,12.84 101.04,12.85 103.87,12.85 103.91,12.84 103.94,12.82 104.82,11.94 104.84,11.91 104.85,11.87 104.85,10.72 104.89,10.57 105.04,10.41 105.05,10.36 105.05,8.49 105.04,8.45 105.02,8.42 104.83,8.23 104.8,8.21 104.76,8.2
LGND on TOP: outline of 206 points within 68.3,2.5 106.5,23 ; 1 cut-out
LGND on TOP: outline of 136 points within 82.38,11.2 106.1,18.7
LGND on BOTTOM: outline of 111 points within 68.3,2.5 106.5,23 ; 4 cut-outs
LGND on CONDUCTIVE2: outline of 90 points within 68.3,2.5 106.5,23 ; 8 cut-outs
LGND on CONDUCTIVE3: outline of 91 points within 68.3,2.5 106.5,23 ; 8 cut-outs
Net_1 on BOTTOM: -1,1 -6,1 -6,99 -1,99 ; 2 cut-outs
Net_2 on BOTTOM: 161,95.79 162.37,95.98 163,97.21 163,99 166,99 166,1 163,1 163,2.79 162.37,4.02 161,4.21 ; 2 cut-outs
Net_3 on CONDUCTIVE3: -6,1 -6,99 -1,99 -1,1
Net_4 on CONDUCTIVE3: 163,1 163,2.79 162.37,4.02 161,4.21 161,95.79 162.37,95.98 163,97.21 163,99 166,99 166,1
Net_5 on CONDUCTIVE2: -6,1 -6,99 -1,99 -1,1
Net_6 on CONDUCTIVE2: 163,1 163,2.79 162.37,4.02 161,4.21 161,95.79 162.37,95.98 163,97.21 163,99 166,99 166,1
Net_7 on TOP: -1,1 -6,1 -6,99 -1,99 ; 2 cut-outs
Net_8 on TOP: 161,95.79 162.37,95.98 163,97.21 163,99 166,99 166,1 163,1 163,2.79 162.37,4.02 161,4.21 ; 2 cut-outs
Net_9 on TOP: 45.98,57.92 45.98,59.45 47.23,59.45 47.23,57.92
Net_10 on TOP: 44.12,65.05 44.12,66.58 45.38,66.58 45.38,65.05
Net_11 on TOP: 45.98,65.05 45.98,66.58 47.23,66.58 47.23,65.05
Net_12 on TOP: 47.83,65.05 47.83,66.58 49.08,66.58 49.08,65.05
O_5V on TOP: 79.52,27.1 79.5,27.1 79.49,27.11 79.21,27.39 79.2,27.4 79.2,27.42 79.2,27.78 79.2,27.8 79.21,27.81 79.49,28.09 79.5,28.1 79.52,28.1 81.1,28.1 81.3,28.3 81.3,32.3 81.31,32.34 81.35,32.35 82.25,32.35 82.29,32.34 82.3,32.3 82.3,31.33 82.4,31.23 82.4,31.21 82.4,27.97 82.4,27.95 82.39,27.94 81.56,27.11 81.55,27.1 81.53,27.1
O_10V on TOP: 81.35,33.55 81.31,33.56 81.3,33.6 81.3,37.01 80.71,37.6 80.7,37.61 80.7,37.63 80.7,40.55 80.71,40.59 80.75,40.6 82.25,40.6 82.29,40.59 82.3,40.55 82.3,35.95 83.09,35.16 83.1,35.15 83.1,35.13 83.1,34.77 83.1,34.75 83.09,34.74 82.91,34.56 82.9,34.55 82.88,34.55 82.45,34.55 82.3,34.4 82.3,33.6 82.29,33.56 82.25,33.55
O_GND on TOP: outline of 246 points within 68.3,2.5 159,97.5 ; 8 cut-outs
O_GND on BOTTOM: 74.35,33.55 75.15,33.55
O_GND on BOTTOM: 76.85,29.5 77.65,29.5
O_GND on BOTTOM: 72.1,25.5 72.9,25.5
O_GND on BOTTOM: 72.1,32.3 72.9,32.3
O_GND on BOTTOM: outline of 613 points within 68.3,2.5 159,97.5 ; 11 cut-outs
O_GND on CONDUCTIVE2: outline of 229 points within 68.3,2.5 159,97.5 ; 42 cut-outs
O_GND on CONDUCTIVE3: 109.17,5.53 109.13,5.53 109.1,5.55 108.75,5.9 108.72,5.97 108.75,6.04 108.87,6.18 109.11,7.48 108,8.21 107.09,8.2 107.05,8.21 107.02,8.23 106.83,8.42 106.81,8.45 106.8,8.49 106.8,8.96 106.77,9.11 106.68,9.24 106.43,9.49 106.41,9.53 106.4,9.57 106.4,13.16 106.37,13.31 106.28,13.44 104.42,15.31 104.29,15.39 104.13,15.43 102.17,15.43 102.13,15.43 102.1,15.45 101.95,15.6 101.93,15.63 101.92,15.67 101.92,15.86 101.93,15.9 101.95,15.93 102.32,16.29 102.4,16.32 102.47,16.29 103.37,15.85 104.27,16.29 104.31,16.31 104.35,16.32 105.18,16.32 105.22,16.32 105.25,16.3 108.2,13.35 108.22,13.32 108.22,13.28 108.22,11.55 108.25,11.41 108.33,11.3 108.34,11.28 113.7,5.93 113.7,5.62 113.67,5.55 113.6,5.53
O_GND on CONDUCTIVE3: outline of 228 points within 68.3,2.5 159,97.5 ; 36 cut-outs
OUT+ on TOP: 127.85,88.56 127.86,88.6 127.88,88.63 128.77,89.52 128.8,89.54 128.84,89.55 149.01,89.55 149.05,89.54 149.08,89.52 154.02,84.58 154.04,84.55 154.05,84.51 154.05,81.15 154.02,81.08 153.95,81.05 149.2,81.05 149.05,80.9 149.2,80.75 153.95,80.75 154.02,80.72 154.05,80.65 154.05,74.85 154.02,74.78 153.95,74.75 149.2,74.75 149.09,74.71 149.05,74.6 149.05,74.4 149.09,74.29 149.2,74.25 153.95,74.25 154.02,74.22 154.05,74.15 154.05,68.35 154.02,68.28 153.95,68.25 149.2,68.25 149.05,68.1 149.2,67.95 153.95,67.95 154.02,67.92 154.05,67.85 154.05,52.02 154.04,51.98 154.02,51.95 152.4,50.33 152.37,50.31 152.33,50.3 136.95,50.3 136.2,49.55 136.2,49 136.17,48.93 136.1,48.9 133.95,48.9 133.7,48.65 133.7,47.24 133.69,47.2 133.67,47.17 133.38,46.88 133.35,46.86 133.31,46.85 118.29,46.85 118.25,46.86 118.22,46.88 116.23,48.87 116.21,48.9 116.2,48.94 116.2,81.36 116.21,81.4 116.23,81.43 118.22,83.42 118.25,83.44 118.29,83.45 127.48,83.45 127.59,83.47 127.69,83.54 127.76,83.61 127.83,83.71 127.85,83.82 ; 6 cut-outs
OUT+ on BOTTOM: outline of 85 points within 116.5,45.7 154.05,83.5 ; 3 cut-outs
PN on TOP: outline of 98 points within 43.75,20.55 55.9,34.65
PN on TOP: 16.2,95.02 20,91.2 23.8,95.02 23.8,97.21 23.81,97.25 23.83,97.28 24.02,97.47 24.05,97.49 24.09,97.5 64.41,97.5 64.45,97.49 64.48,97.47 64.67,97.28 64.69,97.25 64.7,97.21 64.7,2.79 64.69,2.75 64.67,2.72 64.48,2.53 64.45,2.51 64.41,2.5 24.09,2.5 24.05,2.51 24.02,2.53 23.83,2.72 23.81,2.75 23.8,2.79 23.8,4.98 20,8.8 16.2,4.98 16.2,2.79 16.19,2.75 16.17,2.72 15.98,2.53 15.95,2.51 15.91,2.5 9.66,2.5 9.62,2.51 9.59,2.53 9.4,2.72 9.38,2.75 9.37,2.79 9.37,5.55 7.67,9.65 3.57,11.35 1.29,11.35 1.25,11.36 1.22,11.38 1.03,11.57 1.01,11.6 1,11.64 1,88.36 1.01,88.4 1.03,88.43 1.22,88.62 1.25,88.64 1.29,88.65 3.57,88.65 7.67,90.35 9.37,94.45 9.37,97.2 9.38,97.24 9.4,97.27 9.6,97.47 9.63,97.49 9.67,97.5 15.91,97.5 15.95,97.49 15.98,97.47 16.17,97.28 16.19,97.25 16.2,97.21 ; 7 cut-outs
PN on TOP: 47.54,17.1 47.5,17.11 47.47,17.13 44.65,19.95 44.63,19.98 44.62,20.02 44.62,21.6 44.65,21.67 44.73,21.7 45.02,21.7 45.1,21.67 45.12,21.6 45.12,20.87 45.15,20.76 45.21,20.66 45.41,20.46 45.51,20.4 45.62,20.38 46.08,20.38 46.12,20.37 46.15,20.35 46.36,20.14 46.46,20.07 46.57,20.05 47.33,20.05 47.4,20.02 47.42,19.95 47.42,19.67 47.45,19.56 47.51,19.46 47.64,19.34 47.73,19.27 47.85,19.25 48.73,19.25 48.84,19.27 48.94,19.34 49.23,19.62 49.23,19.65 49.25,19.72 49.33,19.75 50.03,19.75 50.14,19.77 50.24,19.84 50.3,19.93 50.33,20.05 50.33,22.25 50.35,22.32 50.42,22.35 50.51,22.35 50.55,22.34 50.58,22.32 50.7,22.2 50.72,22.17 50.73,22.13 50.73,21.9 50.76,21.73 50.86,21.58 50.87,21.57 50.89,21.54 50.9,21.5 50.9,20.18 50.92,20.14 50.92,20.11 50.92,19.55 50.95,19.43 51.01,19.34 51.12,19.23 51.14,19.2 51.15,19.16 51.15,18.32 51.15,18.3 51.15,17.2 51.12,17.13 51.05,17.1
PN on BOTTOM: 16.2,95.02 20,91.2 23.8,95.02 23.8,97.21 23.81,97.25 23.83,97.28 24.02,97.47 24.05,97.49 24.09,97.5 64.41,97.5 64.45,97.49 64.48,97.47 64.67,97.28 64.69,97.25 64.7,97.21 64.7,2.79 64.69,2.75 64.67,2.72 64.48,2.53 64.45,2.51 64.41,2.5 24.09,2.5 24.05,2.51 24.02,2.53 23.83,2.72 23.81,2.75 23.8,2.79 23.8,4.98 20,8.8 16.2,4.98 16.2,2.79 16.19,2.75 16.17,2.72 15.98,2.53 15.95,2.51 15.91,2.5 9.66,2.5 9.62,2.51 9.59,2.53 9.4,2.72 9.38,2.75 9.37,2.79 9.37,5.55 7.67,9.65 3.57,11.35 1.29,11.35 1.25,11.36 1.22,11.38 1.03,11.57 1.01,11.6 1,11.64 1,88.36 1.01,88.4 1.03,88.43 1.22,88.62 1.25,88.64 1.29,88.65 3.57,88.65 7.67,90.35 9.37,94.45 9.37,97.21 9.38,97.25 9.4,97.28 9.59,97.47 9.62,97.49 9.66,97.5 15.91,97.5 15.95,97.49 15.98,97.47 16.17,97.28 16.19,97.25 16.2,97.21 ; 13 cut-outs
PN on CONDUCTIVE2, CONDUCTIVE3: 16.2,95.02 20,91.2 23.8,95.02 23.8,97.21 23.81,97.25 23.83,97.28 24.02,97.47 24.05,97.49 24.09,97.5 64.41,97.5 64.45,97.49 64.48,97.47 64.67,97.28 64.69,97.25 64.7,97.21 64.7,2.79 64.69,2.75 64.67,2.72 64.48,2.53 64.45,2.51 64.41,2.5 24.09,2.5 24.05,2.51 24.02,2.53 23.83,2.72 23.81,2.75 23.8,2.79 23.8,4.98 20,8.8 16.2,4.98 16.2,2.79 16.19,2.75 16.17,2.72 15.98,2.53 15.95,2.51 15.91,2.5 9.66,2.5 9.62,2.51 9.59,2.53 9.4,2.72 9.38,2.75 9.37,2.79 9.37,5.55 7.67,9.65 3.57,11.35 1.29,11.35 1.25,11.36 1.22,11.38 1.03,11.57 1.01,11.6 1,11.64 1,88.36 1.01,88.4 1.03,88.43 1.22,88.62 1.25,88.64 1.29,88.65 3.57,88.65 7.67,90.35 9.37,94.45 9.37,97.21 9.38,97.25 9.4,97.28 9.59,97.47 9.62,97.49 9.66,97.5 15.91,97.5 15.95,97.49 15.98,97.47 16.17,97.28 16.19,97.25 16.2,97.21 ; 38 cut-outs
N03975 on TOP: outline of 137 points within 2.95,39.2 60.65,96.2 ; 3 cut-outs
N04057 on BOTTOM: 40.08,70.28 40.11,70.3 40.14,70.31 40.75,70.62 41.06,71.23 41.07,71.27 41.09,71.29 41.34,71.54 41.36,71.58 41.38,71.6 54.17,84.4 54.2,84.42 54.24,84.42 55.25,84.42 55.32,84.4 55.35,84.33 55.35,83.38 55.67,83.05 60.36,83.05 60.4,83.04 60.43,83.02 60.62,82.83 60.64,82.8 60.65,82.76 60.65,75.59 60.64,75.55 60.62,75.52 60.43,75.33 60.4,75.31 60.36,75.3 54.82,75.3 54.65,75.25 54.57,75.2 46.41,67.03 46.37,67.01 46.33,67 44.15,67 40.68,63.53 40.65,63.51 40.61,63.5 30.94,63.5 30.9,63.51 30.87,63.53 29.58,64.82 29.56,64.85 29.55,64.89 29.55,67.51 29.56,67.55 29.58,67.58 30.87,68.87 30.9,68.89 30.94,68.9 38.7,68.9 ; 3 cut-outs
N04057 on CONDUCTIVE2, CONDUCTIVE3: 30.07,65.62 29.72,65.77 29.57,66.12 29.57,67.33 29.72,67.68 30.07,67.83 34.88,67.83 35.23,67.68 35.38,67.33 35.38,66.12 35.23,65.77 34.88,65.62
N07028 on BOTTOM: 33.39,71.5 33.35,71.51 33.32,71.53 33.18,71.67 33.16,71.7 33.15,71.74 33.15,72.4 33.18,72.47 33.25,72.5 34.4,72.5 34.47,72.47 34.5,72.4 34.5,71.6 34.47,71.53 34.4,71.5
N07195 on TOP: 38.88,59.62 38.8,59.65 38.77,59.73 38.77,60.48 38.8,60.55 38.88,60.58 39.26,60.58 39.3,60.57 39.33,60.55 39.55,60.33 39.57,60.3 39.58,60.26 39.58,59.73 39.55,59.65 39.48,59.62
N07198 on BOTTOM: 33.49,76.38 33.4,76.44 33.42,76.55 34.1,77.22 34.13,77.24 34.17,77.25 34.83,77.25 34.87,77.24 34.9,77.22 35.58,76.55 35.6,76.44 35.51,76.38
N07475 on TOP: outline of 94 points within 36,60.73 60.65,86.1
N07475 on TOP: 52.45,32.83 52.38,32.85 52.35,32.92 52.35,35.88 52.38,35.95 52.45,35.98 53.25,35.98 53.32,35.95 53.35,35.88 53.35,33.2 53.34,33.16 53.32,33.13 53.04,32.85 53.01,32.83 52.97,32.83
N07475 on BOTTOM: 29.85,69.72 29.78,69.75 29.75,69.83 29.75,70.26 29.76,70.3 29.78,70.33 30.32,70.87 30.35,70.89 30.39,70.9 38.16,70.9 38.2,70.89 38.23,70.87 38.57,70.53 38.59,70.5 38.6,70.46 38.6,70.04 38.59,70 38.57,69.97 38.35,69.75 38.32,69.73 38.28,69.72
N07475 on BOTTOM: 52.68,34.15 52.64,34.16 52.61,34.18 51.58,35.21 51.56,35.24 51.55,35.28 51.55,36.25 51.58,36.32 51.65,36.35 53.03,36.35 53.07,36.34 53.1,36.32 53.32,36.1 53.34,36.07 53.35,36.03 53.35,34.47 53.34,34.43 53.32,34.4 53.1,34.18 53.07,34.16 53.03,34.15
N17106 on BOTTOM: 92.8,35 92.73,35.03 92.7,35.1 92.7,37.1 92.73,37.17 92.8,37.2 93.9,37.2 93.97,37.17 94,37.1 94,35.1 93.97,35.03 93.9,35
N17193 on BOTTOM: 92.8,44.55 92.73,44.58 92.7,44.65 92.7,46.65 92.73,46.72 92.8,46.75 93.95,46.75 94.02,46.72 94.05,46.65 94.05,44.65 94.02,44.58 93.95,44.55
N17255 on BOTTOM: 91.25,71.15 91.18,71.18 91.15,71.25 91.15,73.33 91.18,73.4 91.25,73.42 92.35,73.42 92.42,73.4 92.45,73.33 92.45,71.25 92.42,71.18 92.35,71.15
N17411 on BOTTOM: outline of 86 points within 75.2,27.45 91.92,61.2 ; 4 cut-outs
N17449 on BOTTOM: 85.1,95.91 85.11,95.95 85.13,95.98 85.32,96.17 85.35,96.19 85.39,96.2 90.01,96.2 90.05,96.19 90.08,96.17 90.3,95.95 90.32,95.92 90.33,95.88 90.33,79.79 90.31,79.74 90.27,79.7 89.77,78.9 90.27,78.1 90.31,78.06 90.33,78.01 90.33,70.58 90.3,70.52 90.24,70.49 89.5,69.6 90.24,68.71 90.3,68.68 90.33,68.62 90.33,65.22 90.32,65.18 90.3,65.15 90.08,64.93 90.05,64.91 90.01,64.9 88.86,64.9 88.85,64.9 88.21,64.7 87.75,64.21 87.75,64.2 87.6,63.61 87.74,63.01 87.75,62.99 87.75,62.97 87.75,61.79 87.74,61.75 87.72,61.72 87.53,61.53 87.5,61.51 87.46,61.5 84.59,61.5 84.55,61.51 84.52,61.53 84.33,61.72 84.31,61.75 84.3,61.79 84.3,63 83.05,64.71 81.03,64.04 81,64.01 80.95,64 78.4,64 78.33,64.03 78.3,64.09 77.93,64.85 77.14,65.15 74.45,65.15 74.2,65.4 74.2,89.61 74.21,89.65 74.23,89.68 74.42,89.87 74.45,89.89 74.49,89.9 82.03,89.9 82.14,89.92 82.24,89.99 85.01,92.76 85.08,92.86 85.1,92.97 ; 10 cut-outs
N17555 on BOTTOM: 92.14,31.88 92.1,31.88 92.07,31.9 91.68,32.3 91.66,32.33 91.65,32.37 91.65,32.83 91.66,32.87 91.68,32.9 92.55,33.77 92.58,33.79 92.62,33.8 93.9,33.8 93.97,33.77 94,33.7 94,32.34 93.99,32.3 93.97,32.27 93.6,31.9 93.57,31.88 93.53,31.88
N17605 on CONDUCTIVE3: 96.19,32.25 96.15,32.26 96.12,32.28 95.93,32.47 95.91,32.5 95.9,32.54 95.9,34.55 95.93,34.62 96,34.65 97.4,34.65 97.47,34.62 97.5,34.55 97.5,32.84 97.49,32.8 97.47,32.77 96.98,32.28 96.95,32.26 96.91,32.25
N17605 on CONDUCTIVE3: 96,62.7 95.93,62.73 95.9,62.8 95.9,63.55 90.35,69.1 90.19,69.1 90.15,69.11 90.12,69.13 89.93,69.32 89.91,69.35 89.9,69.39 89.9,69.81 89.91,69.85 89.93,69.88 90.8,70.75 90.8,78.15 90.28,78.67 90.26,78.7 90.25,78.74 90.25,79.01 90.26,79.05 90.28,79.08 90.57,79.37 90.6,79.39 90.64,79.4 93.56,79.4 93.6,79.39 93.63,79.37 93.87,79.13 93.89,79.1 93.9,79.06 93.9,78.69 93.89,78.65 93.87,78.62 92.4,77.15 92.4,71.15 93.67,69.88 93.69,69.85 93.7,69.81 93.7,68.05 97.47,64.28 97.49,64.25 97.5,64.21 97.5,62.8 97.47,62.73 97.4,62.7
